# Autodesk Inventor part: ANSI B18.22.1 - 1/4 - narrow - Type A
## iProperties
Comments: To add or edit properties for Autodesk Inventor files, use iProperties.
Created: 2004-12
Part Number: ANSI B18.22.1 - 1/4 - narrow - Type A
Vendor: Autodesk Inc.
Document SubType Name: Modeling
Designer: John Blackburn
Material: Default
Description: Washer A
Standard: ANSI B18.22.1
Size Designation: 1/4 - narrow - Type A
Alert: To add or edit properties for Autodesk Inventor files, use iProperties.
Control State: 0
Master: False
Checked Out: False
Shininess: 64.0
Length Units: 11272
Angle Units: 11279
Time Units: 11290
Mass Units: 11286
Length Display Precision: 3
Angle Display Precision: 2
Compacted: True
Classification: un/spsc 31161807
Density: 0.0
Volumn: 0.0
Area: 0.0
PropertySet Name: Model Information
Author: John Blackburn
Revision Number: 8
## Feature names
1. Body [Extrusion]
